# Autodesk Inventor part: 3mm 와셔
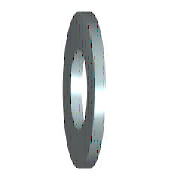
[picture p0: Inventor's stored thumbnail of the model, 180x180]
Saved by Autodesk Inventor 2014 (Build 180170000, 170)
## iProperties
Created: 2012-02
Part Number: 3mm 와셔
Material: 스테인리스강
Description: 평면 와셔 - 대형 시리즈 - 제품 등급 A
Document SubType Name: Modeling
Standard: ISO 7093 A
Designer: mduedu
Standard Revision: First Edition 2000-06-01
Standards Organization: ISO
Language: ko-KR
Size Designation: ST 3 - 140 HV - A
Categories: <MemberInstance><Categories><Category DisplayName="조임쇠" InternalName="e4da775c-781d-43d5-af7c-5136215cf5a6" Mnemonic="FSTN"><Category DisplayName="와셔" InternalN
Density: 8.08 g/cm^3
Appearance: 파란색 - 벽 페인트 - 광택
Mass: 0.359235 g
Surface Area: 1.41811 cm^2
Volume: 0.0444598 cm^3
IsCustomPart: 1
Author: mduedu
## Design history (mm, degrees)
sketch "스케치"
  geometry: C1 r 4.5 at (0, 0); C2 r 1.6 at (0, 0); 1 further point
  constraints: 2 centre point, 2 coincident
  dimensions: "d0" = 3.2 diameter of C2 (= SD1); "d1" = 9 diameter of C1 (= SD2)
extrude "본체" new body sketch "스케치" distance "d2" = 0.8 (= SD); taper "d3" = 0 deg
workaxis "Work Axis1"
workplane "Work Plane1"
sketch "스케치5"
  geometry: 2 further points
  constraints: 1 coincident
body "Solid1"
other parameters: "SD1" = 3.2 [user parameter; used in 1 equation term], "SD2" = 9 [user parameter; used in 1 equation term], "SD" = 0.8 [user parameter; used in 1 equation term], "d4" = 0, "d5" = 0, "d6" = 0, "d7" = 0, "NND" = 3 [user parameter]
